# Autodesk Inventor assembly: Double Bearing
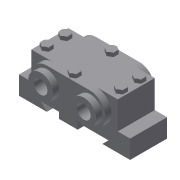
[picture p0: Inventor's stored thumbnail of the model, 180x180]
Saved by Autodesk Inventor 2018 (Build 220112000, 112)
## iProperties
Shininess: 64.0
Length Units: 11269
Angle Units: 11279
Time Units: 11290
Mass Units: 11283
Length Display Precision: 3
Angle Display Precision: 2
Created: 2002-02
Part Number: Double Bearing
Document SubType Name: Assembly
Designer: ***
Density: 0.0
Volumn: 0.0
Area: 0.0
PropertySet Name: Model Information
Control State: 0
Master: False
Checked Out: False
Author: ***
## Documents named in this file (5)
- E:\_Deepak\Inventor\Autodesk Inventor_2017_Project\Resources\Inventor_2017_tut\c10_Inv_tut_2017\c10_tut03_inv\Double Bearing Assembly\Double Bearing.iam
- E:\_Deepak\Inventor\Autodesk Inventor_2017_Project\Resources\Inventor_2017_tut\c10_Inv_tut_2017\c10_tut03_inv\Double Bearing Assembly\Base.ipt
- E:\_Deepak\Inventor\Autodesk Inventor_2017_Project\Resources\Inventor_2017_tut\c10_Inv_tut_2017\c10_tut03_inv\Double Bearing Assembly\Cap.ipt
- E:\_Deepak\Inventor\Autodesk Inventor_2017_Project\Resources\Inventor_2017_tut\c10_Inv_tut_2017\c10_tut03_inv\Double Bearing Assembly\Bushing.ipt
- E:\_Deepak\Inventor\Autodesk Inventor_2017_Project\Resources\Inventor_2017_tut\c10_Inv_tut_2017\c10_tut03_inv\Double Bearing Assembly\Bolt.ipt
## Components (10 placed, 4 different names)
1. Base:1 — Insert:1, Insert:2
2. Cap:1 — Insert:1, Insert:2, Insert:3, Insert:4, Insert:5, Insert:6
3. Bushing:1 — Insert:3
4. Bushing:2 — Insert:4
5. Bolt:1 — Insert:5
6. Bolt:6
7. Bolt:7
8. Bolt:8
9. Bolt:5 — Insert:6
10. Bolt:9
## Component patterns: Component Pattern 1 (4 elements), Component Pattern 2 (2 elements)
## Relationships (6: Insert 6)
- Insert:1: Base:1 ↔ Cap:1
- Insert:2: Base:1 ↔ Cap:1
- Insert:3: Cap:1 ↔ Bushing:1
- Insert:4: Cap:1 ↔ Bushing:2
- Insert:5: Cap:1 ↔ Bolt:1
- Insert:6: Cap:1 ↔ Bolt:5
